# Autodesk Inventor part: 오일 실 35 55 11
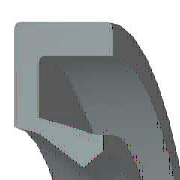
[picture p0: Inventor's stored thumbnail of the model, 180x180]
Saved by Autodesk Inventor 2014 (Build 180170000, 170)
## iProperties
IsCustomPart: 1
Created: 2012-02
Part Number: 오일 실 35 55 11
Material: 고무
Description: 오일 실 - 비스프링, 조립 GA
Document SubType Name: Modeling
Standard: JIS B 2402
Designer: mdu-01
Standards Organization: JIS
Language: ko-KR
Size Designation: 35 55 11 A
Categories: <MemberInstance><Categories><Category DisplayName="샤프트 부품" InternalName="7f7aeb1f-a693-4053-b835-cee3144e0d98" Mnemonic="SHFT"><Category DisplayName="실링" Intern
Density: 0.93 g/cm^3
Appearance: Rubber-Black
Author: mdu-01
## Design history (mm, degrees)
body "Solid1"
revolve "회전1" stored, may be unused: angle "d27" = 360 deg
fillet "모깎기1" dims "d28" = 0.55 (= 0.05 x b)
sketch "스케치2"
  geometry: L1 (20.786, -8.25)-(21.786, -11); L2 (19.452, -7.563)-(20.786, -8.25); L3 (17.5, -3.025)-(19.452, -7.563); L4 (19.038, -1.65)-(17.5, -3.025); L5 (23.5, -9.625)-(19.038, -1.65); L6 (23.5, -0.55)-(23.5, -9.625); L7 (25.5, -0.55)-(23.5, -0.55); L8 (25.5, 0)-(25.5, -0.55); L9 (27.5, 0)-(25.5, 0); L10 (27.5, -11)-(27.5, 0); L11 (21.786, -11)-(27.5, -11); L12 (0, -9.6)-(0, 1.6) reference; L13 (28, 0)-(14, 0) reference
  constraints: 22 end point, 3 horizontal, 3 vertical
  dimensions: "d2" = 11 distance of L10.start L9.start (= b); "d4" = 2 distance of L9.start L8.start (= 0.1 x dd - 0.1 x Diam); "d6" = 0.55 distance of L8.start L7.start (= 0.05 x b); "d8" = 1.53846 horizontal distance of L4.start L3.start (= 0.0769231 x dd - 0.0769231 x Diam); "d10" = 1.375 vertical distance of L5.start L10.start (= 0.125 x b); "d12" = 2 distance of L7.start L6.start (= 0.1 x dd - 0.1 x Diam); "d14" = 1.1 vertical distance of L4.start L6.start (= 0.1 x b); "d16" = 5.71429 distance of L1.end L10.start (= 0.285714 x dd - 0.285714 x Diam); "d18" = 1 horizontal distance of L1.start L1.end (= 0.05 x dd - 0.05 x Diam); "d20" = 1.375 vertical distance of L4.start L3.start (= 0.125 x b); "d22" = 2.75 vertical distance of L1.start L1.end (= 0.25 x b); "d24" = 1.33333 horizontal distance of L2.start L1.start (= 0.0666667 x dd - 0.0666667 x Diam); "d26" = 0.6875 vertical distance of L2.start L1.start (= 0.0625 x b); "d29" = 0 distance between parallel lines of L13 L9; "d30" = 17.5 distance from line of L3.start L12 (= 0.5 x Diam); "d31" = 27.5 distance between parallel lines of L12 L10 (= 0.5 x dd)
other parameters: "dd" = 55 [user parameter; used in 7 equation terms], "Diam" = 35 [user parameter; used in 7 equation terms], "b" = 11 [user parameter; used in 8 equation terms], "d1" = 8 (derived), "d3" = 2 (derived), "d5" = 0.4 (derived), "d7" = 1.53846 (derived), "d9" = 1 (derived), "d11" = 2 (derived), "d13" = 0.8 (derived), "d15" = 5.71429 (derived), "d17" = 1 (derived), "d19" = 1 (derived), "d21" = 2 (derived), "d23" = 1.33333 (derived), "d25" = 0.5 (derived), "d32" = 0
